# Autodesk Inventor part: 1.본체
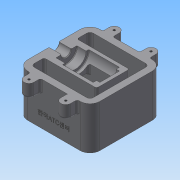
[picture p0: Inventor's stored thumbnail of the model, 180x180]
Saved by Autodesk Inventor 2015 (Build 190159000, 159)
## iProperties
Created: 2018-01
Part Number: 1.본체
Material: 일반
Document SubType Name: Modeling
Designer: user
Density: 1 g/cm^3
Appearance: 기본값
Author: user
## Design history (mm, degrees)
sketch "스케치1"
  geometry: L1 (-55, -55)-(55, -55); L2 (55, -55)-(55, 55); L3 (55, 55)-(-55, 55); L4 (-55, 55)-(-55, -55); L5 (-55, -55)-(55, 55); L6 (55, -55)-(-55, 55); 1 further point
  constraints: 12 end point, 2 midpoint, 2 parallel, 1 horizontal, 1 perpendicular
  dimensions: "d0" = 110 distance of L1.end L2.end; "d1" = 110 distance of L2.end L3.end
extrude "돌출1" new body sketch "스케치1" stored distance "d2" = 65; taper "d3" = 0 deg
fillet "모깎기1" dims "d4" = 15
sketch "스케치13" dims "d0" = 110, "d1" = 110
  geometry: L1 (80, -65)-(0, -65) reference; L2 (95, -65)-(95, 0) reference; 2 further points
  constraints: 1 other
  dimensions: "d79" = 55 distance from line of L2 point (40, -45); "d80" = 20 distance from line of L1 point (40, -45)
feature "엠보싱1" sketch "스케치13" dims "d0" = 110, "d1" = 110, "d5" = 10, "d6" = 10, "d7" = 5, "d81" = 0.5, "d82" = 0
sketch "스케치2"
  geometry: L1 (40, 55)-(-40, 55) reference; L2 (-55, 40)-(-55, -40) reference; L3 (40, -45)-(-40, -45); L4 (-45, -40)-(-45, 40); L5 (-40, 45)-(40, 45); L6 (45, 40)-(45, -40); L7 (45, -45)-(-45, 45); L8 (-45, -45)-(45, 45); A1 r 5 centre (-40, 40) between (-40, 45) and (-45, 40); A2 r 5 centre (40, 40) between (45, 40) and (40, 45); A3 r 5 centre (40, -40) between (40, -45) and (45, -40); A4 r 5 centre (-40, -40) between (-45, -40) and (-40, -45); 1 further point
  constraints: 12 end point, 8 point on circle, 8 point on line, 8 tangent, 4 centre point, 3 equal radius, 2 midpoint, 2 parallel, 1 horizontal, 1 perpendicular
  dimensions: "d5" = 10 distance between parallel lines of L2 L4; "d6" = 10 distance between parallel lines of L1 L5; "d7" = 5 radius of A1
extrude "돌출2" cut sketch "스케치2" distance "d8" = 65; taper "d9" = 0 deg
sketch "스케치3"
  geometry: L1 (-55, 40)-(-55, -40) reference; L2 (-40, -55)-(40, -55) reference; L3 (-28, -65)-(28, -65); L4 (-20.5, -65)-(-20.5, -55); L5 (-35.5, -65)-(-35.5, -55); A1 r 7.5 centre (-28, -65) between (-35.5, -65) and (-20.5, -65); 1 further point
  constraints: 6 end point, 3 point on line, 2 perpendicular, 2 point on circle, 2 tangent, 1 centre point, 1 coincident, 1 horizontal
  dimensions: "d11" = 56 distance of L3.start L3.end; "d12" = 27 distance from line of L1 L3.start; "d13" = 10 distance between parallel lines of L3 L2; "d15" = 7.5 radius of A1
extrude "돌출3" join sketch "스케치3" distance "d16" = 20; taper "d17" = 0 deg
sketch "스케치4"
  geometry: L1 (55, -32.5)-(40, -32.5) reference; L2 (45, 32.5)-(45, -32.5) reference; L3 (45, -23.936)-(-35, -2.5); L4 (-55, 32.5)-(-55, -32.5) reference; L5 (40, 32.5)-(-40, 32.5) reference; L6 (-35, -2.5)-(-35, 32.5); L7 (45, 32.5)-(-35, 32.5); L8 (45, 32.5)-(45, -23.936); 1 further point
  constraints: 8 end point, 2 perpendicular, 2 point on line, 1 collinear
  dimensions: "d18" = 105 deg angle of L2 L3; "d19" = 20 distance from line of L4 L3.end; "d20" = 30 vertical distance of L4.end L3.end
extrude "돌출4" join sketch "스케치4" stored distance "d21" = 50; taper "d22" = 0 deg
sketch "스케치5"
  geometry: L1 (55, -32.5)-(55, 32.5) reference; L2 (55, 32.5)-(-30, 32.5); L3 (45, 32.5)-(-35, 32.5) reference; L4 (55, 32.5)-(55, 40); L5 (55, 40)-(36, 40); L6 (36, 40)-(36, 47.5); L7 (35, 48.5)-(22, 48.5); L8 (22, 48.5)-(22, 51.5); L9 (21, 52.5)-(-24, 52.5); L10 (-25, 51.5)-(-25, 47.5); L11 (-25, 47.5)-(-29, 47.5); L12 (-30, 46.5)-(-30, 32.5); A1 r 1 centre (-29, 46.5) between (-29, 47.5) and (-30, 46.5); A2 r 1 centre (-24, 51.5) between (-24, 52.5) and (-25, 51.5); A3 r 1 centre (21, 51.5) between (22, 51.5) and (21, 52.5); A4 r 1 centre (35, 47.5) between (36, 47.5) and (35, 48.5); 5 further points
  constraints: 20 end point, 9 point on line, 8 point on circle, 8 tangent, 4 centre point, 4 vertical, 3 equal radius, 2 perpendicular, 1 horizontal, 1 parallel
  dimensions: "d24" = 15 diameter of L5 L2; "d25" = 32 diameter of L7 L2; "d26" = 40 diameter of L9 L2; "d28" = 30 diameter of L11 L2; "d29" = 19 distance of L4.end L5.end; "d30" = 14 distance of point (36, 48.5) L7.end; "d31" = 47 distance of point (22, 52.5) point (-25, 52.5); "d32" = 5 distance of L10.end point (-30, 47.5); "d33" = 1 radius of A1
revolve "회전1" sketch "스케치5" stored, may be unused: angle "d34" = 90 deg
sketch "스케치8"
  geometry: L1 (55, -21.439)-(-20, -1.343); L2 (-35, -2.5)-(45, -23.936) reference; L3 (21, 12.5)-(-24, 12.5) reference; L4 (17, 26.343)-(-20, 26.343); L5 (-20, 26.343)-(-20, -1.343); L6 (17, 7.573)-(17, 26.343); L7 (17, 26.343)-(-20, -1.343); L8 (-20, 26.343)-(17, -1.343); L9 (55, -32.5)-(55, 32.5) reference; L10 (55, -2.609)-(17, 7.573); 2 further points
  constraints: 14 end point, 3 midpoint, 3 parallel, 2 point on line, 1 horizontal, 1 perpendicular
  dimensions: "d40" = 5 distance between parallel lines of L2 L1; "d42" = 37 distance of L4.start L4.end; "d48" = 27.68571 distance of L4.end L1.end; "d49" = 18.18874 distance between parallel lines of L1 L10
extrude "돌출5" cut sketch "스케치8" stored distance "d50" = 30; taper "d51" = 0 deg
sketch "스케치9"
  geometry: A1 r 7.5 centre (-28, -65) between (-35.5, -65) and (-20.5, -65) reference; A2 r 7.5 centre (28, -65) between (20.5, -65) and (35.5, -65) reference; A3 r 7.5 centre (28, 65) between (35.5, 65) and (20.5, 65) reference; A4 r 7.5 centre (-28, 65) between (-20.5, 65) and (-35.5, 65) reference; 5 further points
  constraints: 4 coincident
hole "구멍1" sketch "스케치9" at (-28, -65), (28, -65), (28, 65), (-28, 65) diameter "d52" = 3.242; stored, may be unused: countersink angle "d56" = 90 deg, drill point angle "d58" = 118 deg; dims "d53" = 9, "d54" = 4, "d55" = 2, "d57" = 11
fillet "모깎기2" dims "d59" = 3
fillet "모깎기3" dims "d60" = 3
fillet "모깎기4" dims "d61" = 3
fillet "모깎기5" dims "d62" = 3
fillet "모깎기6" dims "d63" = 3
fillet "모깎기7" dims "d64" = 3
chamfer "모따기1" distance "d65" = 1; stored, may be unused: second distance "d66" = 2, angle "d67" = 45 deg
chamfer "모따기2" distance "d76" = 1; stored, may be unused: second distance "d77" = 2, angle "d78" = 45 deg
node "솔리드1"
mirror "대칭1"
mirror "대칭2"
